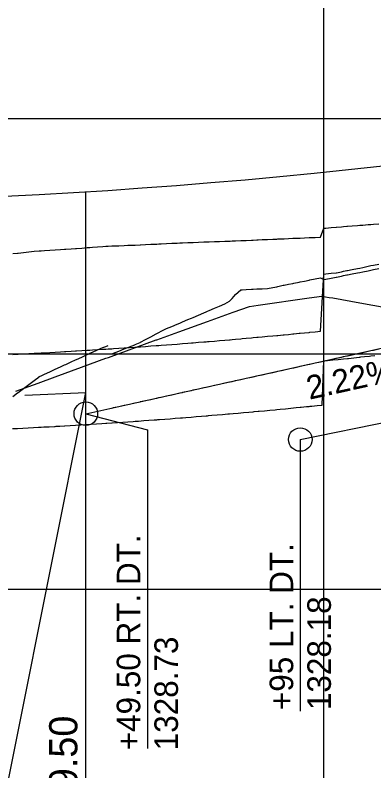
# Model space of a CAD drawing. Extents: x 1371206 to 1374178, y 379328 to 381511.
# Drawn here: x 1372379.1 to 1372455.2, y 379509.7 to 379670.4 of the extents above; entities that cross this region are included whole.
import ezdxf

# ---------------------------------------------------------------- set-up
doc = ezdxf.new("R2010")
doc.units = 0
for name, color, linetype in [('37', 7, 'Continuous'), ('BRIDGE', 7, 'Continuous'), ('R_Exist Surface', 7, 'Continuous'), ('R_Profile Work Left', 7, 'Continuous'), ('R_Profile Work Right', 7, 'Continuous'), ('R_Vert Alg', 7, 'Continuous'), ('R_Vert Alg Annot', 7, 'Continuous')]:
    doc.layers.add(name, color=color, linetype=linetype)

msp = doc.modelspace()

# ---------------------------------------------------------------- linework, layer by layer
at = {"layer": '37'}
for p, q in [((1372444.63, 379348.35), (1372444.63, 379798.35)), ((1371244.63, 379648.35), (1374144.63, 379648.35)), ((1371244.63, 379598.35), (1372944.63, 379598.35)), ((1371244.63, 379598.35), (1374144.63, 379598.35)), ((1371244.63, 379548.35), (1374144.63, 379548.35))]:
    msp.add_line(p, q, dxfattribs=at)
at = {"layer": 'BRIDGE'}
for p in [(1372381.18, 379589.58), (1372394.13, 379460.86)]:
    msp.add_line(p, (1372394.13, 379590.12), dxfattribs=at)
for points in [[(1372394.13, 379590.12), (1372394.13, 379632.82)], [(1372371.78, 379478.35), (1372394.13, 379590.12)]]:
    msp.add_lwpolyline(points, dxfattribs=at)
at = {"layer": 'R_Exist Surface'}
msp.add_lwpolyline([(1372379.25, 379590.45), (1372384, 379592.16), (1372387.61, 379593.5), (1372393.2, 379595.57), (1372398.39, 379597.42), (1372398.91, 379597.61), (1372409.07, 379601.34), (1372409.16, 379601.37), (1372413.86, 379603.02), (1372419.94, 379605.25), (1372425.36, 379607.22), (1372428.88, 379608.45), (1372430.71, 379608.72), (1372441.49, 379610.27), (1372444.19, 379610.65), (1372445.74, 379610.31), (1372446.57, 379610.24), (1372452.26, 379609.23), (1372457.78, 379608.2)], dxfattribs=at)
at = {"layer": 'R_Profile Work Left'}
for points in [[(1372378.63, 379619.67), (1372379.63, 379619.79), (1372379.76, 379619.8), (1372380.88, 379619.94), (1372380.88, 379619.94), (1372382.01, 379620.07), (1372383.14, 379620.16), (1372384.23, 379620.23), (1372384.26, 379620.24), (1372384.63, 379620.26), (1372385.39, 379620.32), (1372386.51, 379620.39), (1372387.61, 379620.47), (1372387.64, 379620.47), (1372388.76, 379620.55), (1372389.63, 379620.61), (1372389.89, 379620.63), (1372391.01, 379620.71), (1372391.95, 379620.77), (1372392.14, 379620.79), (1372393.26, 379620.86), (1372394.39, 379620.94), (1372394.63, 379620.96), (1372394.94, 379620.98), (1372394.99, 379620.98), (1372395.51, 379621.02), (1372396.64, 379621.12), (1372397.77, 379621.21), (1372398.39, 379621.25), (1372398.89, 379621.27), (1372399.63, 379621.3), (1372400.02, 379621.31), (1372401.14, 379621.35), (1372402.27, 379621.39), (1372403.02, 379621.43), (1372403.39, 379621.45), (1372404.52, 379621.5), (1372404.63, 379621.5), (1372405.64, 379621.55), (1372405.76, 379621.55), (1372406.77, 379621.6), (1372407.89, 379621.65), (1372409.02, 379621.7), (1372409.16, 379621.71), (1372409.63, 379621.73), (1372410.14, 379621.76), (1372411.27, 379621.81), (1372412.4, 379621.86), (1372413.52, 379621.91), (1372414.09, 379621.93), (1372414.63, 379621.96), (1372414.65, 379621.96), (1372415.77, 379622.01), (1372416.53, 379622.04), (1372416.9, 379622.06), (1372418.02, 379622.11), (1372419.15, 379622.15), (1372419.63, 379622.16), (1372419.94, 379622.18), (1372420.27, 379622.19), (1372421.4, 379622.22), (1372422.52, 379622.26), (1372423.65, 379622.3), (1372424.63, 379622.34), (1372424.78, 379622.34), (1372425.16, 379622.36), (1372425.9, 379622.39), (1372427.03, 379622.44), (1372427.3, 379622.45), (1372428.15, 379622.49), (1372429.28, 379622.54), (1372429.63, 379622.55), (1372430.4, 379622.59), (1372430.71, 379622.6), (1372431.53, 379622.64), (1372432.65, 379622.68), (1372433.78, 379622.73), (1372434.63, 379622.77), (1372434.9, 379622.78), (1372436.03, 379622.83), (1372436.22, 379622.84), (1372437.15, 379622.88), (1372438.06, 379622.92), (1372438.28, 379622.93), (1372439.41, 379622.97), (1372439.63, 379622.98), (1372440.53, 379623.02), (1372441.49, 379623.06), (1372441.66, 379623.07), (1372442.78, 379623.12), (1372443.91, 379623.16), (1372444.63, 379625.06), (1372445.03, 379625.1), (1372446.16, 379625.2), (1372447.28, 379625.29), (1372447.29, 379625.29), (1372448.41, 379625.39), (1372448.83, 379625.43), (1372449.53, 379625.49), (1372449.63, 379625.5), (1372450.66, 379625.59), (1372451.78, 379625.67), (1372452.26, 379625.71), (1372452.91, 379625.75), (1372454.04, 379625.84), (1372454.63, 379625.88), (1372455.16, 379625.92), (1372456.29, 379626)], [(1372378.55, 379582.48), (1372379.63, 379582.53), (1372379.66, 379582.53), (1372380.78, 379582.59), (1372381.89, 379582.65), (1372383.01, 379582.7), (1372384.12, 379582.76), (1372384.63, 379582.79), (1372385.24, 379582.83), (1372386.35, 379582.89), (1372387.46, 379582.95), (1372387.61, 379582.96), (1372387.82, 379582.97), (1372388.58, 379583.01), (1372389.63, 379583.07), (1372389.69, 379583.08), (1372390.81, 379583.14), (1372391.92, 379583.21), (1372393.04, 379583.28), (1372394.13, 379583.35), (1372394.15, 379583.35), (1372394.63, 379583.38), (1372395.27, 379583.42), (1372396.38, 379583.49), (1372397.5, 379583.56), (1372398.39, 379583.62), (1372398.6, 379583.63), (1372398.61, 379583.63), (1372399.63, 379583.7), (1372399.73, 379583.71), (1372400.84, 379583.78), (1372401.96, 379583.86), (1372403.07, 379583.94), (1372404.18, 379584.01), (1372404.63, 379584.05), (1372405.3, 379584.09), (1372406.41, 379584.17), (1372407.53, 379584.25), (1372408.64, 379584.34), (1372409.16, 379584.37), (1372409.38, 379584.39), (1372409.63, 379584.41), (1372409.76, 379584.42), (1372410.87, 379584.5), (1372411.99, 379584.59), (1372413.1, 379584.67), (1372414.22, 379584.76), (1372414.63, 379584.79), (1372415.33, 379584.85), (1372416.45, 379584.94), (1372417.56, 379585.03), (1372418.68, 379585.12), (1372419.63, 379585.2), (1372419.79, 379585.21), (1372419.94, 379585.22), (1372420.16, 379585.24), (1372420.9, 379585.3), (1372422.02, 379585.4), (1372423.13, 379585.49), (1372424.25, 379585.59), (1372424.63, 379585.62), (1372425.36, 379585.69), (1372426.48, 379585.78), (1372427.59, 379585.88), (1372428.71, 379585.98), (1372429.63, 379586.07), (1372429.82, 379586.08), (1372430.71, 379586.17), (1372430.94, 379586.19), (1372430.94, 379586.19), (1372432.05, 379586.29), (1372433.17, 379586.39), (1372434.28, 379586.5), (1372434.63, 379586.53), (1372435.39, 379586.61), (1372436.51, 379586.71), (1372437.62, 379586.82), (1372438.74, 379586.93), (1372439.63, 379587.02), (1372439.85, 379587.04), (1372440.97, 379587.15), (1372441.49, 379587.2), (1372441.73, 379587.23), (1372442.08, 379587.26), (1372443.2, 379587.38), (1372444.31, 379587.49), (1372444.63, 379596.86), (1372445.43, 379596.94), (1372446.54, 379597.06), (1372447.66, 379597.18), (1372448.77, 379597.29), (1372449.63, 379597.39), (1372449.89, 379597.41), (1372451, 379597.53), (1372452.11, 379597.66), (1372452.26, 379597.67), (1372452.51, 379597.7), (1372453.23, 379597.78), (1372454.34, 379597.9), (1372454.63, 379597.93), (1372455.46, 379598.03)]]:
    msp.add_lwpolyline(points, dxfattribs=at)
at = {"layer": 'R_Profile Work Right'}
for points in [[(1372378.63, 379598.24), (1372379.63, 379598.29), (1372379.76, 379598.3), (1372380.88, 379598.36), (1372380.88, 379598.36), (1372382.01, 379598.42), (1372383.14, 379598.48), (1372384.23, 379598.53), (1372384.26, 379598.54), (1372384.63, 379598.56), (1372385.39, 379598.6), (1372386.51, 379598.66), (1372387.61, 379598.72), (1372387.64, 379598.72), (1372388.76, 379598.79), (1372389.63, 379598.84), (1372389.89, 379598.85), (1372391.01, 379598.92), (1372391.95, 379598.98), (1372392.14, 379598.99), (1372393.26, 379599.06), (1372394.39, 379599.13), (1372394.63, 379599.14), (1372394.94, 379599.16), (1372394.99, 379599.16), (1372395.51, 379599.2), (1372396.64, 379599.27), (1372397.77, 379599.34), (1372398.39, 379599.38), (1372398.89, 379599.41), (1372399.63, 379599.46), (1372400.02, 379599.49), (1372401.14, 379599.56), (1372402.27, 379599.64), (1372403.02, 379599.69), (1372403.39, 379599.72), (1372404.52, 379599.8), (1372404.63, 379599.8), (1372405.64, 379599.88), (1372405.76, 379599.88), (1372406.77, 379599.96), (1372407.89, 379600.04), (1372409.02, 379600.12), (1372409.16, 379600.13), (1372409.63, 379600.16), (1372410.14, 379600.2), (1372411.27, 379600.29), (1372412.4, 379600.37), (1372413.52, 379600.46), (1372414.09, 379600.5), (1372414.63, 379600.55), (1372414.65, 379600.55), (1372415.77, 379600.64), (1372416.53, 379600.7), (1372416.9, 379600.73), (1372418.02, 379600.82), (1372419.15, 379600.91), (1372419.63, 379600.95), (1372419.94, 379600.97), (1372420.27, 379601), (1372421.4, 379601.09), (1372422.52, 379601.19), (1372423.65, 379601.28), (1372424.63, 379601.37), (1372424.78, 379601.38), (1372425.16, 379601.41), (1372425.9, 379601.48), (1372427.03, 379601.58), (1372427.3, 379601.6), (1372428.15, 379601.68), (1372429.28, 379601.78), (1372429.63, 379601.81), (1372430.4, 379601.88), (1372430.71, 379601.91), (1372431.53, 379601.98), (1372432.65, 379602.09), (1372433.78, 379602.19), (1372434.63, 379602.27), (1372434.9, 379602.3), (1372436.03, 379602.4), (1372436.22, 379602.42), (1372437.15, 379602.51), (1372438.06, 379602.6), (1372438.28, 379602.62), (1372439.41, 379602.73), (1372439.63, 379602.75), (1372440.53, 379602.84), (1372441.49, 379602.93), (1372441.66, 379602.95), (1372442.78, 379603.06), (1372443.91, 379603.18), (1372444.63, 379615.33), (1372445.03, 379615.38), (1372446.16, 379615.49), (1372447.28, 379615.61), (1372447.29, 379615.61), (1372448.41, 379615.83), (1372448.83, 379615.91), (1372449.53, 379616.06), (1372449.63, 379616.08), (1372450.66, 379616.28), (1372451.78, 379616.51), (1372452.26, 379616.61), (1372452.91, 379616.75), (1372454.04, 379616.98), (1372454.63, 379617.11), (1372455.16, 379617.22), (1372456.29, 379617.46)], [(1372399.63, 379598.38), (1372400.02, 379598.53), (1372401.14, 379598.97), (1372402.27, 379599.42), (1372403.02, 379599.71), (1372403.39, 379599.86), (1372404.52, 379600.3), (1372404.63, 379600.35), (1372405.64, 379600.79), (1372405.76, 379600.86), (1372406.77, 379601.4), (1372407.89, 379602), (1372409.02, 379602.61), (1372409.16, 379602.68), (1372409.63, 379602.93), (1372410.14, 379603.21), (1372411.27, 379603.72), (1372412.4, 379604.2), (1372413.52, 379604.68), (1372414.09, 379604.92), (1372414.63, 379605.15), (1372414.65, 379605.16), (1372415.77, 379605.64), (1372416.53, 379605.96), (1372416.9, 379606.12), (1372418.02, 379606.6), (1372419.15, 379607.08), (1372419.63, 379607.29), (1372419.94, 379607.42), (1372420.27, 379607.56), (1372421.4, 379608.05), (1372422.52, 379608.53), (1372423.65, 379609.01), (1372424.63, 379609.55), (1372424.78, 379609.71), (1372425.16, 379610.13), (1372425.9, 379610.95), (1372427.03, 379611.99), (1372427.3, 379612), (1372428.15, 379612.05), (1372429.28, 379612.1), (1372429.63, 379612.12), (1372430.4, 379612.16), (1372430.71, 379612.18), (1372431.53, 379612.22), (1372432.65, 379612.28), (1372433.78, 379612.47), (1372434.63, 379612.64), (1372434.9, 379612.7), (1372436.03, 379612.93), (1372436.22, 379612.97), (1372437.15, 379613.16), (1372438.06, 379613.34), (1372438.28, 379613.39), (1372439.41, 379613.61), (1372439.63, 379613.66), (1372440.53, 379613.84), (1372441.49, 379614.04), (1372441.66, 379614.07), (1372442.78, 379614.3), (1372443.91, 379614.53), (1372444.63, 379614.15), (1372445.03, 379614.23), (1372446.16, 379614.46), (1372447.28, 379614.69), (1372447.29, 379614.69), (1372448.41, 379614.91), (1372448.83, 379615), (1372449.53, 379615.14), (1372449.63, 379615.16), (1372450.66, 379615.36), (1372451.78, 379615.59), (1372452.26, 379615.68), (1372452.91, 379615.81), (1372454.04, 379616.04), (1372454.63, 379616.15), (1372455.16, 379616.26), (1372456.29, 379616.5)], [(1372396.64, 379599.25), (1372397.77, 379599.71), (1372398.39, 379599.96), (1372398.89, 379600.16)], [(1372378.63, 379589.32), (1372379.63, 379590.06), (1372379.76, 379590.16), (1372380.88, 379590.99), (1372380.88, 379591), (1372382.01, 379591.84), (1372383.14, 379592.68), (1372384.23, 379593.5), (1372384.26, 379593.52), (1372384.63, 379593.7), (1372385.39, 379594.05), (1372386.51, 379594.57), (1372387.61, 379595.08), (1372387.64, 379595.09), (1372388.76, 379595.61), (1372389.63, 379596.01), (1372389.89, 379596.13), (1372391.01, 379596.65), (1372391.95, 379597.08), (1372392.14, 379597.17), (1372393.26, 379597.69), (1372394.39, 379598.21), (1372394.63, 379598.32), (1372394.94, 379598.47), (1372394.99, 379598.49), (1372395.51, 379598.73), (1372396.64, 379599.25)], [(1372399.63, 379586.85), (1372400.02, 379586.94), (1372401.14, 379587.19), (1372402.27, 379587.44), (1372403.02, 379587.6), (1372403.39, 379587.69), (1372404.52, 379587.94), (1372404.63, 379587.96), (1372405.64, 379588.19), (1372405.76, 379588.21), (1372406.77, 379588.44), (1372407.89, 379588.69), (1372409.02, 379588.94), (1372409.16, 379588.97), (1372409.63, 379589.07), (1372410.14, 379589.19), (1372411.27, 379589.44), (1372412.4, 379589.69), (1372413.52, 379589.94), (1372414.09, 379590.06), (1372414.63, 379590.18), (1372414.65, 379590.19), (1372415.77, 379590.44), (1372416.53, 379590.6), (1372416.9, 379590.69), (1372418.02, 379590.94), (1372419.15, 379591.19), (1372419.63, 379591.29), (1372419.94, 379591.36), (1372420.27, 379591.44), (1372421.4, 379591.69), (1372422.52, 379591.94), (1372423.65, 379592.19), (1372424.63, 379592.4), (1372424.78, 379592.44), (1372425.16, 379592.52), (1372425.9, 379592.69), (1372427.03, 379592.94), (1372427.3, 379593), (1372428.15, 379593.19), (1372429.28, 379593.43), (1372429.63, 379593.51), (1372430.4, 379593.68), (1372430.71, 379593.75), (1372431.53, 379593.93), (1372432.65, 379594.18), (1372433.78, 379594.43), (1372434.63, 379594.62), (1372434.9, 379594.68), (1372436.03, 379594.93), (1372436.22, 379594.98), (1372437.15, 379595.18), (1372438.06, 379595.39), (1372438.28, 379595.43), (1372439.41, 379595.68), (1372439.63, 379595.73), (1372440.53, 379595.93), (1372441.49, 379596.15), (1372441.66, 379596.18), (1372442.78, 379596.43), (1372443.91, 379596.68), (1372444.63, 379596.84), (1372445.03, 379596.93), (1372446.16, 379597.18), (1372447.28, 379597.43), (1372447.29, 379597.44), (1372448.41, 379597.68), (1372448.83, 379597.78), (1372449.53, 379597.93), (1372449.63, 379597.95), (1372450.66, 379598.18), (1372451.78, 379598.43), (1372452.26, 379598.54), (1372452.91, 379598.68), (1372454.04, 379598.93), (1372454.63, 379599.07), (1372455.16, 379599.18), (1372456.29, 379599.43)]]:
    msp.add_lwpolyline(points, dxfattribs=at)
at = {"layer": 'R_Vert Alg'}
for p, q in [((1372394.13, 379585.63), (1372544.63, 379619.05)), ((1372439.63, 379580.15), (1372535.92, 379599.97))]:
    msp.add_line(p, q, dxfattribs=at)
msp.add_lwpolyline([(1372376.92, 379631.86), (1372384.21, 379632.24), (1372391.51, 379632.65), (1372398.8, 379633.11), (1372406.09, 379633.62), (1372413.38, 379634.16), (1372420.67, 379634.75), (1372427.96, 379635.38), (1372435.26, 379636.06), (1372442.55, 379636.78), (1372449.84, 379637.54), (1372457.13, 379638.34)], dxfattribs=at)
for centre in [(1372394.13, 379585.65), (1372439.63, 379580.15)]:
    msp.add_circle(centre, 2.5, dxfattribs=at)
at = {"layer": 'R_Vert Alg Annot'}
msp.add_line((1372439.63, 379580.15), (1372439.63, 379522.43), dxfattribs=at)
msp.add_lwpolyline([(1372394.13, 379585.65), (1372407.18, 379582.22), (1372407.18, 379514.49)], dxfattribs=at)

# ---------------------------------------------------------------- texts
at = {"layer": 'BRIDGE'}
msp.add_text('STA. 211+49.50', height=6, rotation=90, dxfattribs=at).set_placement((1372392.34, 379463.26))
at = {"layer": 'R_Vert Alg Annot'}
for s, rotation, p in [('2.22% RT.DT.GR.', 12.5204, (1372441.56, 379588.61)), ('+49.50 RT. DT.', 90, (1372405.68, 379514.11)), ('+95 LT. DT.', 90, (1372438.13, 379522.65)), ('1328.18', 90, (1372446.13, 379522.65)), ('1328.73', 90, (1372413.68, 379514.11))]:
    msp.add_text(s, height=5, rotation=rotation, dxfattribs=at).set_placement(p)

doc.saveas('drawing.dxf')
